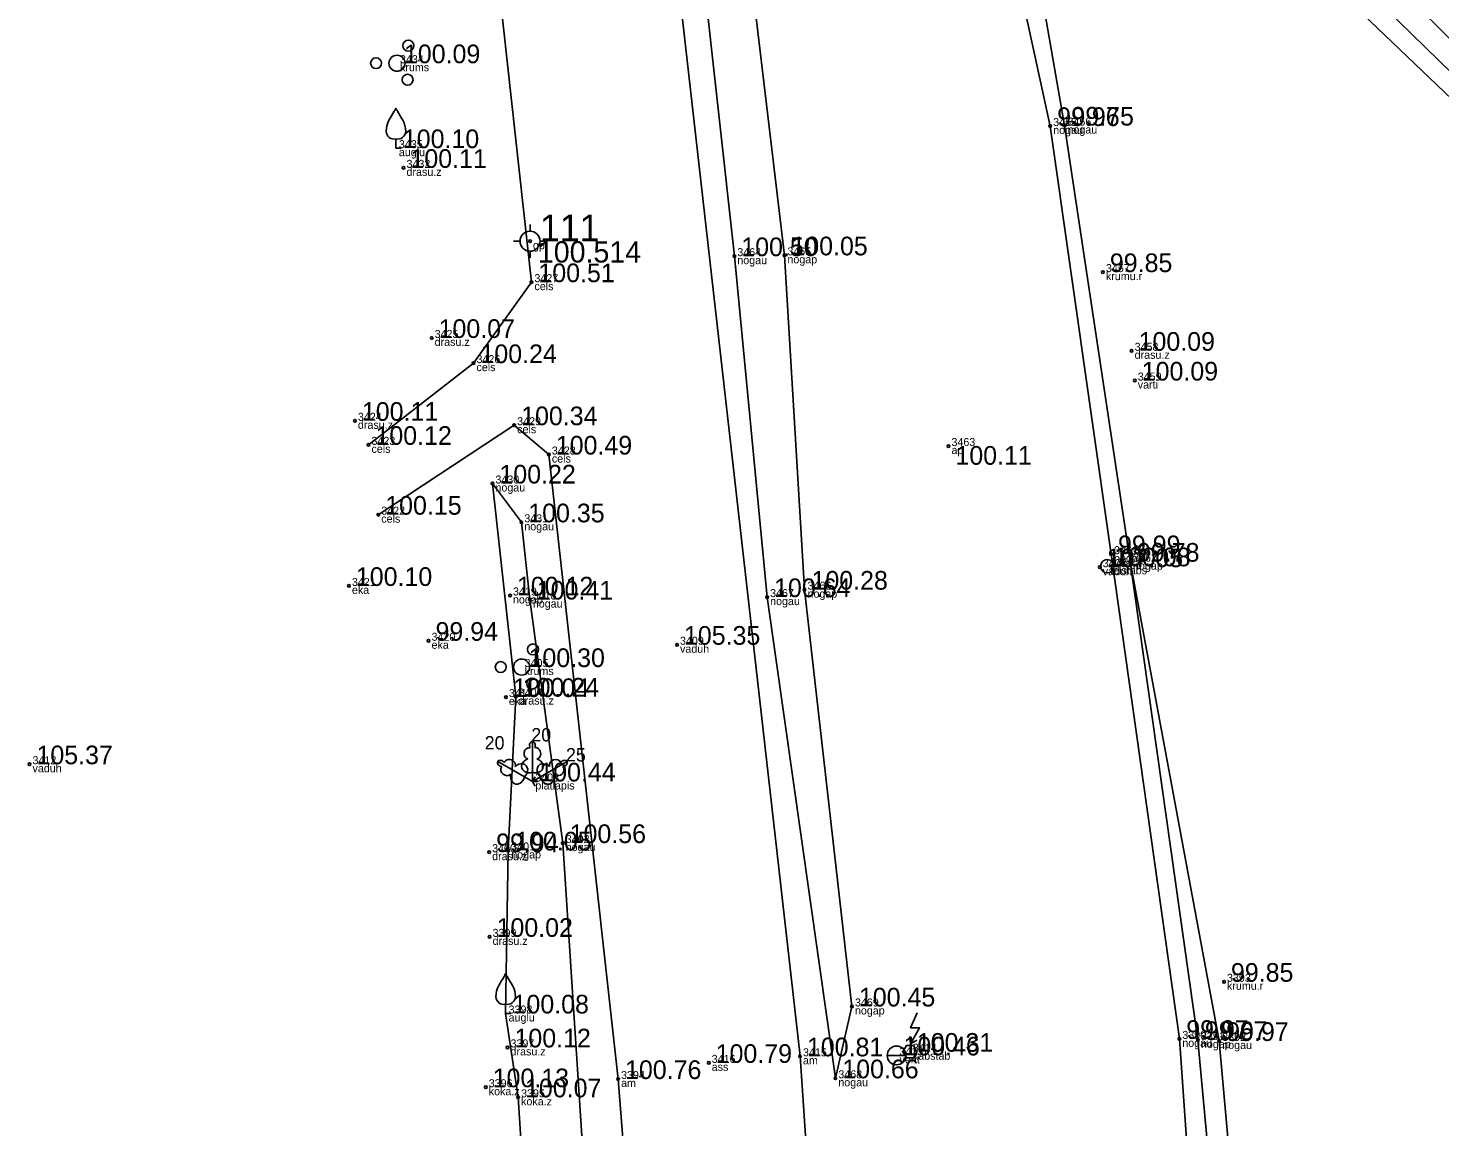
# Model space of a CAD drawing. Extents: x 614911 to 615803, y 262110 to 264311.
# Drawn here: x 615597.1 to 615650.1, y 264027.5 to 264068.6 of the extents above; entities that cross this region are included whole.
import ezdxf

# ---------------------------------------------------------------- set-up
doc = ezdxf.new("R2010")
doc.units = 0
for name, color, linetype in [('Level 1', 7, 'Continuous'), ('Level 12', 7, 'Continuous'), ('Level 19', 7, 'Continuous'), ('Level 31', 7, 'Continuous'), ('Level 37', 7, 'Continuous'), ('Level 49', 7, 'Continuous'), ('Level 53', 7, 'Continuous'), ('Level 54', 7, 'Continuous'), ('Level 57', 7, 'Continuous'), ('Level 58', 7, 'Continuous')]:
    doc.layers.add(name, color=color, linetype=linetype)

msp = doc.modelspace()

# ---------------------------------------------------------------- linework, layer by layer
at = {"layer": 'Level 1'}
for p, q in [((615610.929, 264064.499), (615610.929, 264064.147)), ((615610.929, 264064.147), (615611.129, 264064.147)), ((615615.745, 264040.577), (615616.046, 264040.404)), ((615616.046, 264040.751), (615616.046, 264040.404)), ((615616.046, 264040.404), (615616.146, 264040.577)), ((615616.347, 264040.577), (615616.046, 264040.404)), ((615616.046, 264040.404), (615616.246, 264040.404)), ((615616.046, 264040.404), (615616.146, 264040.231)), ((615615.043, 264032.058), (615615.043, 264031.706)), ((615615.043, 264031.706), (615615.243, 264031.706))]:
    msp.add_line(p, q, dxfattribs=at)
for points in [[(615616.046, 264041.904), (615616.046, 264040.751)], [(615616.136, 264041.672), (615616.135, 264041.673)], [(615614.747, 264041.154), (615615.745, 264040.577)], [(615614.993, 264041.115), (615614.992, 264041.115)], [(615617.345, 264041.154), (615616.347, 264040.577)], [(615617.189, 264040.96), (615617.189, 264040.962)]]:
    msp.add_lwpolyline(points, dxfattribs=at)
for centre, radius in [((615611.397, 264067.992), 0.207), ((615610.186, 264067.332), 0.204), ((615610.97, 264067.332), 0.301), ((615611.365, 264066.712), 0.205), ((615616.069, 264045.354), 0.207), ((615614.858, 264044.694), 0.204), ((615615.642, 264044.694), 0.301), ((615616.037, 264044.074), 0.205)]:
    msp.add_circle(centre, radius, dxfattribs=at)
for centre, radius, start, end in [((615623.554, 264057.751), 14.88, 148.4844, 149.9901), ((615610.512, 264065.785), 0.439, 324.3837, 341.712), ((615611.346, 264065.785), 0.439, 198.288, 215.6163), ((615598.304, 264057.751), 14.88, 30.0099, 31.5156), ((615611.453, 264064.772), 0.89, 151.757, 179.9138), ((615610.405, 264064.772), 0.89, 0.0862, 28.243), ((615610.853, 264064.778), 0.29, 181.0782, 285.2823), ((615611.005, 264064.778), 0.29, 254.7177, 358.9218), ((615614.626, 264033.344), 0.439, 324.3837, 341.712), ((615615.46, 264033.344), 0.439, 198.288, 215.6163), ((615615.567, 264032.331), 0.89, 151.757, 179.9138), ((615627.668, 264025.31), 14.88, 148.4844, 149.9901), ((615602.418, 264025.31), 14.88, 30.0099, 31.5156), ((615614.519, 264032.331), 0.89, 0.0862, 28.243), ((615614.967, 264032.337), 0.29, 181.0782, 285.2823), ((615615.119, 264032.337), 0.29, 254.7177, 358.9218)]:
    msp.add_arc(centre, radius, start, end, dxfattribs=at)
for centre, major_axis, ratio, start_param, end_param in [((615615.918, 264041.459), (-0.039, -0.212), 0.861323, 3.141593, 6.283185), ((615616.046, 264041.754), (0, -0.15), 0.707107, 3.14537, 5.287485), ((615616.046, 264041.754), (0, -0.15), 0.707107, 0.995701, 3.137816), ((615616.174, 264041.459), (0.039, -0.212), 0.861323, 0, 3.141593), ((615614.877, 264041.079), (0.13, -0.075), 0.707107, 3.14537, 5.287485), ((615614.877, 264041.079), (0.13, -0.075), 0.707107, 0.995701, 3.137816), ((615615.196, 264041.043), (0.203, -0.073), 0.861323, 0, 3.141593), ((615615.577, 264040.778), (-0.236, -0.218), 0.814445, 1.531171, 4.712389), ((615615.956, 264040.997), (0.307, 0.095), 0.814445, 1.570796, 4.752015), ((615616.136, 264040.997), (-0.307, 0.095), 0.814445, 1.531171, 4.712389), ((615616.515, 264040.778), (0.236, -0.218), 0.814445, 1.570796, 4.752015), ((615616.896, 264041.043), (-0.203, -0.073), 0.861323, 3.141593, 6.283185), ((615617.215, 264041.079), (-0.13, -0.075), 0.707107, 3.14537, 5.287485), ((615617.215, 264041.079), (-0.13, -0.075), 0.707107, 0.995701, 3.137816), ((615615.068, 264040.82), (0.165, -0.14), 0.861323, 3.141593, 6.283185), ((615615.488, 264040.623), (0.071, 0.313), 0.814445, 1.570796, 4.752015), ((615616.604, 264040.623), (-0.071, 0.313), 0.814445, 1.531171, 4.712389), ((615617.024, 264040.82), (-0.165, -0.14), 0.861323, 0, 3.141593)]:
    msp.add_ellipse(centre, major_axis=major_axis, ratio=ratio, start_param=start_param, end_param=end_param, dxfattribs=at)
at = {"layer": 'Level 12'}
for p, q in [((615630.225, 264030.572), (615630.466, 264030.711)), ((615629.35, 264030.132), (615630.052, 264030.132))]:
    msp.add_line(p, q, dxfattribs=at)
for points in [[(615630.474, 264031.734), (615630.225, 264031.171), (615630.561, 264031.171), (615630.225, 264030.572)], [(615630.203, 264030.842), (615630.225, 264030.572)]]:
    msp.add_lwpolyline(points, dxfattribs=at)
msp.add_lwpolyline([(615630.069, 264030.042), (615630.335, 264030.042), (615630.468, 264030.272), (615630.335, 264030.503), (615630.069, 264030.503), (615629.936, 264030.272)], close=True, dxfattribs=at)
msp.add_circle((615629.701, 264030.132), 0.351, dxfattribs=at)
at = {"layer": 'Level 19'}
for p, q in [((615615.957, 264061.034), (615615.957, 264061.284)), ((615615.332, 264060.659), (615615.582, 264060.659)), ((615616.332, 264060.659), (615616.582, 264060.659)), ((615615.957, 264060.034), (615615.957, 264060.284))]:
    msp.add_line(p, q, dxfattribs=at)
for radius in [0.375, 0.05]:
    msp.add_circle((615615.957, 264060.659), radius, dxfattribs=at)
at = {"layer": 'Level 31'}
msp.add_lwpolyline([(615622.276, 264096.149), (615620.306, 264095.492), (615619.992, 264093.829), (615623.077, 264091.526), (615628.403, 264085.985), (615633.079, 264081.77), (615638.24, 264077.73), (615652.762, 264063.841), (615653.996, 264062.544), (615654.864, 264062.801), (615654.923, 264063.787), (615640.592, 264078.098), (615635.032, 264083.097)], close=True, dxfattribs=at)
for points in [[(615620.792, 264094.933), (615623.833, 264092.63), (615634.023, 264082.334), (615639.953, 264077.285), (615653.571, 264063.99)], [(615627.407, 264029.276), (615628.03, 264031.969), (615626.252, 264047.596), (615625.498, 264060.129), (615622.838, 264082.468)], [(615621.215, 264081.865), (615623.62, 264060.098), (615624.849, 264047.316), (615627.407, 264029.276)], [(615644.392, 263989.414), (615643.34, 263990.099), (615643.118, 263994.158), (615641.428, 264009.987), (615641.041, 264018.626), (615641.061, 264020.005), (615640.305, 264030.753), (615637.746, 264048.925), (615635.464, 264064.977), (615634.003, 264071.709), (615634.502, 264073.617)], [(615634.502, 264073.617), (615635.999, 264064.995), (615638.458, 264048.645), (615641.004, 264030.71), (615642.1, 264018.821), (615642.898, 264009.911), (615644.133, 263994.406), (615644.364, 263990.22)], [(615614.55, 264051.575), (615615.424, 264043.587), (615615.143, 264037.818), (615615.043, 264031.706), (615615.511, 264028.563), (615616.6, 264011.472), (615617.656, 264000.051), (615618.983, 263989.394), (615619.14, 263984.548), (615620.715, 263982.661)], [(615620.715, 263982.661), (615619.995, 263989.211), (615619.241, 263998.748), (615618.938, 264000.798), (615618.893, 264011.894), (615617.184, 264038.095), (615615.951, 264047.225), (615615.632, 264050.12), (615614.55, 264051.575)], [(615638.458, 264048.645), (615641.802, 264030.675), (615642.708, 264020.483), (615643.913, 264009.698), (615645.33, 263994.078), (615645.663, 263990.026), (615644.392, 263989.414)]]:
    msp.add_lwpolyline(points, dxfattribs=at)
at = {"layer": 'Level 37'}
for points in [[(615611.39, 264101.136), (615616.012, 264059.123), (615613.839, 264056.088), (615609.902, 264053.024)], [(615679.97, 263896.398), (615656.772, 263909.292), (615645.962, 263915.344), (615640.907, 263918.389), (615638.105, 263921.472), (615635.532, 263926.063), (615633.264, 263930.679), (615632.042, 263938.695), (615631.566, 263946.615), (615629.518, 263979.123), (615626.081, 264030.1), (615620.246, 264081.541), (615619.215, 264095.372), (615620.245, 264096.475), (615622.383, 264096.938), (615624.444, 264095.361), (615631.917, 264088.483), (615633.918, 264086.774), (615642.182, 264078.442), (615648.763, 264072.267), (615656.466, 264064.293), (615658.546, 264062.514)], [(615610.269, 264050.406), (615615.365, 264053.76), (615616.665, 264052.661), (615619.26, 264029.249), (615620.506, 264013.545), (615622.506, 263981.182), (615623.215, 263965.211), (615621.82, 263963.492), (615620.117, 263963.482), (615610.522, 263967.156), (615610.153, 263967.974), (615607.063, 263969.517)]]:
    msp.add_lwpolyline(points, dxfattribs=at)
at = {"layer": 'Level 49'}
msp.add_circle((615637.6, 264048.472), 0.25, dxfattribs=at)
at = {"layer": 'Level 57'}
for centre in [(615635.464, 264064.977), (615635.999, 264064.995), (615611.215, 264063.408), (615623.62, 264060.098), (615625.498, 264060.129), (615616.012, 264059.123), (615637.44, 264059.5), (615612.27, 264057.032), (615638.517, 264056.551), (615613.839, 264056.088), (615638.635, 264055.435), (615609.393, 264053.925), (615615.365, 264053.76), (615609.902, 264053.024), (615616.665, 264052.661), (615631.649, 264052.979), (615614.55, 264051.575), (615610.269, 264050.406), (615615.632, 264050.12), (615637.746, 264048.925), (615637.321, 264048.438), (615638.458, 264048.645), (615609.168, 264047.735), (615615.207, 264047.378), (615626.252, 264047.596), (615615.951, 264047.225), (615624.849, 264047.316), (615612.154, 264045.679), (615621.47, 264045.53), (615615.055, 264043.569), (615615.424, 264043.587), (615597.192, 264041.05), (615615.143, 264037.818), (615617.184, 264038.095), (615614.426, 264037.753), (615614.443, 264034.579), (615641.98, 264032.895), (615628.03, 264031.969), (615615.115, 264030.434), (615640.305, 264030.753), (615641.004, 264030.71), (615641.802, 264030.675), (615626.081, 264030.1), (615622.659, 264029.854), (615614.298, 264028.941), (615619.26, 264029.249), (615627.407, 264029.276), (615615.511, 264028.563)]:
    msp.add_circle(centre, 0.05, dxfattribs=at)
at = {"layer": 'Level 58'}
for centre in [(615635.464, 264064.977), (615635.999, 264064.995), (615611.215, 264063.408), (615623.62, 264060.098), (615625.498, 264060.129), (615616.012, 264059.123), (615637.44, 264059.5), (615612.27, 264057.032), (615638.517, 264056.551), (615613.839, 264056.088), (615638.635, 264055.435), (615609.393, 264053.925), (615615.365, 264053.76), (615609.902, 264053.024), (615616.665, 264052.661), (615631.649, 264052.979), (615614.55, 264051.575), (615610.269, 264050.406), (615615.632, 264050.12), (615637.746, 264048.925), (615637.321, 264048.438), (615638.458, 264048.645), (615609.168, 264047.735), (615615.207, 264047.378), (615626.252, 264047.596), (615615.951, 264047.225), (615624.849, 264047.316), (615612.154, 264045.679), (615621.47, 264045.53), (615615.055, 264043.569), (615615.424, 264043.587), (615597.192, 264041.05), (615615.143, 264037.818), (615617.184, 264038.095), (615614.426, 264037.753), (615614.443, 264034.579), (615641.98, 264032.895), (615628.03, 264031.969), (615615.115, 264030.434), (615640.305, 264030.753), (615641.004, 264030.71), (615641.802, 264030.675), (615626.081, 264030.1), (615622.659, 264029.854), (615614.298, 264028.941), (615619.26, 264029.249), (615627.407, 264029.276), (615615.511, 264028.563)]:
    msp.add_circle(centre, 0.05, dxfattribs=at)

# ---------------------------------------------------------------- texts
at = {"layer": 'Level 1'}
for s, p in [(' 20', (615614.072, 264041.604)), (' 20', (615615.821, 264041.904)), (' 25', (615617.12, 264041.154))]:
    msp.add_text(s, height=0.5, dxfattribs=at).set_placement(p)
at = {"layer": 'Level 19'}
for s, height, p in [(' 111', 1, (615615.957, 264060.659)), (' 100.514', 0.8, (615615.957, 264059.859))]:
    msp.add_text(s, height=height, dxfattribs=at).set_placement(p)
at = {"layer": 'Level 53'}
for s, p in [(' krums', (615610.97, 264067.032)), (' nogau', (615635.464, 264064.677)), (' nogau', (615635.999, 264064.695)), (' auglu', (615610.929, 264063.847)), (' drasu.z', (615611.215, 264063.108)), (' gp', (615615.957, 264060.359)), (' nogau', (615623.62, 264059.798)), (' nogap', (615625.498, 264059.829)), (' cels', (615616.012, 264058.823)), (' krumu.r', (615637.44, 264059.2)), (' drasu.z', (615612.27, 264056.732)), (' drasu.z', (615638.517, 264056.251)), (' cels', (615613.839, 264055.788)), (' varti', (615638.635, 264055.135)), (' drasu.z', (615609.393, 264053.625)), (' cels', (615615.365, 264053.46)), (' cels', (615609.902, 264052.724)), (' cels', (615616.665, 264052.361)), (' ap', (615631.649, 264052.679)), (' nogau', (615614.55, 264051.275)), (' cels', (615610.269, 264050.106)), (' nogau', (615615.632, 264049.82)), (' vaduh', (615637.321, 264048.138)), (' telstabs', (615637.6, 264048.172)), (' nogau', (615637.746, 264048.625)), (' nogap', (615638.458, 264048.345)), (' eka', (615609.168, 264047.435)), (' nogap', (615626.252, 264047.296)), (' nogap', (615615.207, 264047.078)), (' nogau', (615615.951, 264046.925)), (' nogau', (615624.849, 264047.016)), (' eka', (615612.154, 264045.379)), (' vaduh', (615621.47, 264045.23)), (' krums', (615615.642, 264044.394)), (' eka', (615615.055, 264043.269)), (' drasu.z', (615615.424, 264043.287)), (' vaduh', (615597.192, 264040.75)), (' platlapis', (615616.046, 264040.104)), (' nogau', (615617.184, 264037.795)), (' drasu.z', (615614.426, 264037.453)), (' nogap', (615615.143, 264037.518)), (' drasu.z', (615614.443, 264034.279)), (' krumu.r', (615641.98, 264032.595)), (' auglu', (615615.043, 264031.406)), (' nogap', (615628.03, 264031.669)), (' drasu.z', (615615.115, 264030.134)), (' nogau', (615640.305, 264030.453)), (' nogap', (615641.004, 264030.41)), (' nogau', (615641.802, 264030.375)), (' am', (615626.081, 264029.8)), (' vent', (615629.701, 264029.832)), (' kabstab', (615630.202, 264029.972)), (' ass', (615622.659, 264029.554)), (' koka.z', (615614.298, 264028.641)), (' am', (615619.26, 264028.949)), (' nogau', (615627.407, 264028.976)), (' koka.z', (615615.511, 264028.263))]:
    msp.add_text(s, height=0.3, dxfattribs=at).set_placement(p)
at = {"layer": 'Level 54'}
for s, p in [(' 3434', (615610.97, 264067.332)), (' 3455', (615635.464, 264064.977)), (' 3456', (615635.999, 264064.995)), (' 3435', (615610.929, 264064.147)), (' 3432', (615611.215, 264063.408)), (' 3464', (615623.62, 264060.098)), (' 3465', (615625.498, 264060.129)), (' 3457', (615637.44, 264059.5)), (' 3427', (615616.012, 264059.123)), (' 3425', (615612.27, 264057.032)), (' 3426', (615613.839, 264056.088)), (' 3458', (615638.517, 264056.551)), (' 3459', (615638.635, 264055.435)), (' 3424', (615609.393, 264053.925)), (' 3429', (615615.365, 264053.76)), (' 3423', (615609.902, 264053.024)), (' 3463', (615631.649, 264052.979)), (' 3428', (615616.665, 264052.661)), (' 3430', (615614.55, 264051.575)), (' 3422', (615610.269, 264050.406)), (' 3431', (615615.632, 264050.12)), (' 3461', (615637.746, 264048.925)), (' 3408', (615637.321, 264048.438)), (' 3460', (615637.6, 264048.472)), (' 3462', (615638.458, 264048.645)), (' 3421', (615609.168, 264047.735)), (' 3419', (615615.207, 264047.378)), (' 3418', (615615.951, 264047.225)), (' 3467', (615624.849, 264047.316)), (' 3466', (615626.252, 264047.596)), (' 3420', (615612.154, 264045.679)), (' 3409', (615621.47, 264045.53)), (' 3405', (615615.642, 264044.694)), (' 3417', (615615.055, 264043.569)), (' 3404', (615615.424, 264043.587)), (' 3412', (615597.192, 264041.05)), (' 3403', (615616.046, 264040.404)), (' 3402', (615617.184, 264038.095)), (' 3400', (615614.426, 264037.753)), (' 3401', (615615.143, 264037.818)), (' 3399', (615614.443, 264034.579)), (' 3393', (615641.98, 264032.895)), (' 3469', (615628.03, 264031.969)), (' 3398', (615615.043, 264031.706)), (' 3390', (615640.305, 264030.753)), (' 3391', (615641.004, 264030.71)), (' 3392', (615641.802, 264030.675)), (' 3397', (615615.115, 264030.434)), (' 3414', (615630.202, 264030.272)), (' 3416', (615622.659, 264029.854)), (' 3415', (615626.081, 264030.1)), (' 3413', (615629.701, 264030.132)), (' 3394', (615619.26, 264029.249)), (' 3468', (615627.407, 264029.276)), (' 3396', (615614.298, 264028.941)), (' 3395', (615615.511, 264028.563))]:
    msp.add_text(s, height=0.3, dxfattribs=at).set_placement(p)
at = {"layer": 'Level 58'}
for s, p in [(' 100.09', (615610.97, 264067.332)), (' 99.96', (615635.464, 264064.977)), (' 99.75', (615635.999, 264064.995)), (' 100.10', (615610.929, 264064.147)), (' 100.11', (615611.215, 264063.408)), (' 100.50', (615623.62, 264060.098)), (' 100.05', (615625.498, 264060.129)), (' 99.85', (615637.44, 264059.5)), (' 100.51', (615616.012, 264059.123)), (' 100.07', (615612.27, 264057.032)), (' 100.09', (615638.517, 264056.551)), (' 100.24', (615613.839, 264056.088)), (' 100.09', (615638.635, 264055.435)), (' 100.11', (615609.393, 264053.925)), (' 100.34', (615615.365, 264053.76)), (' 100.12', (615609.902, 264053.024)), (' 100.49', (615616.665, 264052.661)), (' 100.11', (615631.649, 264052.279)), (' 100.22', (615614.55, 264051.575)), (' 100.15', (615610.269, 264050.406)), (' 100.35', (615615.632, 264050.12)), (' 99.99', (615637.746, 264048.925)), (' 107.05', (615637.321, 264048.438)), (' 100.08', (615637.6, 264048.472)), (' 99.78', (615638.458, 264048.645)), (' 100.10', (615609.168, 264047.735)), (' 100.12', (615615.207, 264047.378)), (' 100.41', (615615.951, 264047.225)), (' 100.64', (615624.849, 264047.316)), (' 100.28', (615626.252, 264047.596)), (' 99.94', (615612.154, 264045.679)), (' 105.35', (615621.47, 264045.53)), (' 100.30', (615615.642, 264044.694)), (' 100.04', (615615.055, 264043.569)), (' 100.24', (615615.424, 264043.587)), (' 105.37', (615597.192, 264041.05)), (' 100.44', (615616.046, 264040.404)), (' 99.94', (615614.426, 264037.753)), (' 100.05', (615615.143, 264037.818)), (' 100.56', (615617.184, 264038.095)), (' 100.02', (615614.443, 264034.579)), (' 99.85', (615641.98, 264032.895)), (' 100.45', (615628.03, 264031.969)), (' 100.08', (615615.043, 264031.706)), (' 100.12', (615615.115, 264030.434)), (' 100.31', (615630.202, 264030.272)), (' 99.97', (615640.305, 264030.753)), (' 99.67', (615641.004, 264030.71)), (' 99.97', (615641.802, 264030.675)), (' 100.79', (615622.659, 264029.854)), (' 100.81', (615626.081, 264030.1)), (' 100.46', (615629.701, 264030.132)), (' 100.76', (615619.26, 264029.249)), (' 100.66', (615627.407, 264029.276)), (' 100.13', (615614.298, 264028.941)), (' 100.07', (615615.511, 264028.563))]:
    msp.add_text(s, height=0.7, dxfattribs=at).set_placement(p)

doc.saveas('drawing.dxf')
